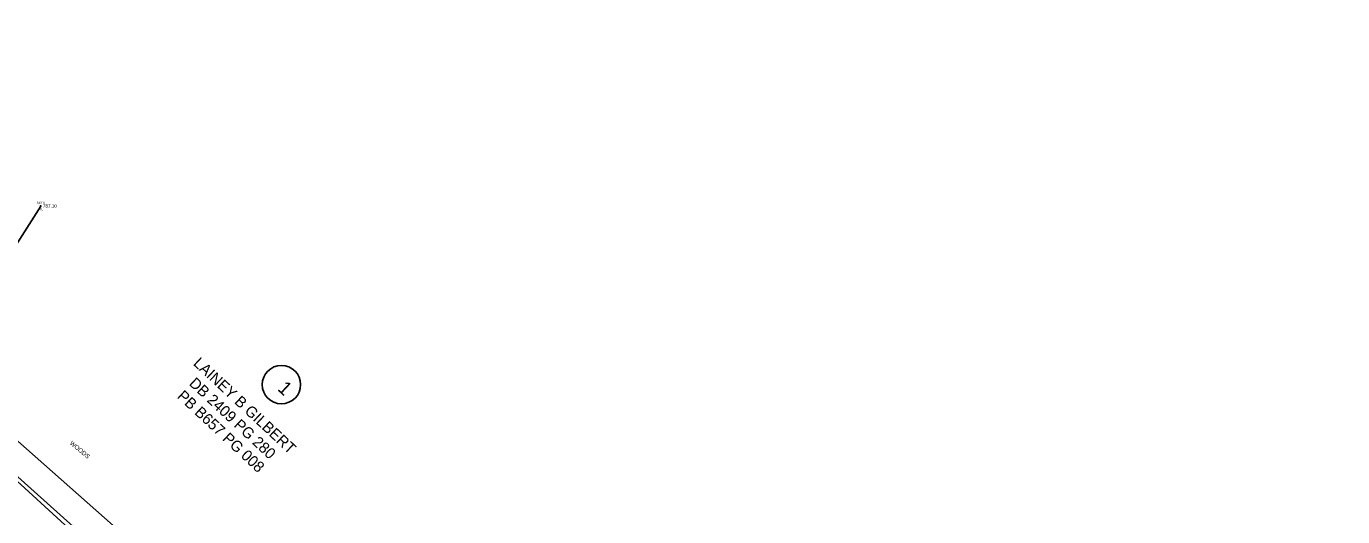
# Model space of a CAD drawing. Extents: x 1378245 to 1381654, y 996521 to 1000567.
# Drawn here: x 1378854 to 1379454, y 999748 to 999972 of the extents above; entities that cross this region are included whole.
import ezdxf

# ---------------------------------------------------------------- set-up
doc = ezdxf.new("R2010")
doc.units = 0
for name, color, linetype in [('RD_EX_DV_TX_Prop(Owner ID)', 7, 'Continuous'), ('RD_EX_RW', 7, 'Continuous'), ('RD_EX_SU_Elec', 7, 'Continuous'), ('RD_EX_TX_VEG_ELEV', 7, 'Continuous'), ('RD_EX_VEG', 7, 'Continuous'), ('RD_EX_VEG_txCode', 7, 'Continuous'), ('RD_SMD_Locator', 7, 'Continuous'), ('RD_TX_Misc2', 7, 'Continuous')]:
    doc.layers.add(name, color=color, linetype=linetype)

msp = doc.modelspace()

# ---------------------------------------------------------------- linework, layer by layer
at = {"layer": 'RD_EX_DV_TX_Prop(Owner ID)'}
msp.add_circle((1378970.68, 999808.1), 8.75, dxfattribs=at)
at = {"layer": 'RD_EX_RW'}
msp.add_line((1378622.31, 999971.52), (1379434.58, 999231.49), dxfattribs=at)
at = {"layer": 'RD_EX_SU_Elec'}
msp.add_lwpolyline([(1378514.25, 999944.12), (1378777.7, 999831.22), (1379190.17, 999461.05), (1379403.33, 999174.04), (1379756.94, 998924.25), (1380051.16, 998659.97), (1380327.91, 998390.65), (1380546.23, 998058.37)], dxfattribs=at)
at = {"layer": 'RD_EX_VEG'}
msp.add_lwpolyline([(1378860.93, 999889.56), (1378813.43, 999815), (1379096.96, 999564.16), (1379102.39, 999570.14)], dxfattribs=at)
at = {"layer": 'RD_SMD_Locator'}
msp.add_circle((1378860.93, 999889.56), 0.15, dxfattribs=at)

# ---------------------------------------------------------------- texts
at = {"layer": 'RD_EX_DV_TX_Prop(Owner ID)'}
for s, height, rotation, p in [('LAINEY B GILBERT', 5, 317.0049, (1378930.13, 999817.36)), ('DB 2409 PG 280', 5, 317.0049, (1378928.23, 999808.2)), ('1', 6.25, 317.00489, (1378968.54, 999805.81)), ('PB B657 PG 008', 5, 317.0049, (1378922.8, 999802.32))]:
    msp.add_text(s, height=height, rotation=rotation, dxfattribs=at).set_placement(p)
at = {"layer": 'RD_EX_TX_VEG_ELEV'}
msp.add_text('787.10', height=1.5, dxfattribs=at).set_placement((1378861.93, 999888.81))
at = {"layer": 'RD_EX_VEG_txCode'}
for s, p in [('54018', (1378859.1, 999890.56)), ('+TL', (1378859.67, 999887.56))]:
    msp.add_text(s, height=1, dxfattribs=at).set_placement(p)
at = {"layer": 'RD_TX_Misc2'}
msp.add_text('WOODS', height=2, rotation=320.50519, dxfattribs=at).set_placement((1378874, 999781.03))

doc.saveas('drawing.dxf')
